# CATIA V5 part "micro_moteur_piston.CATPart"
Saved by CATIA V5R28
Part number: Part6
Bounding box of the stored display mesh (mm): x -13 to 13, y -13 to 13, z 0 to 14.558
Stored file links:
  D:\SAVE\Mécanique\Cotation ISO\Cotation GPS Exercices\Exo 1 ISO GPS\exo1_piston.CATPart
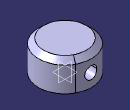
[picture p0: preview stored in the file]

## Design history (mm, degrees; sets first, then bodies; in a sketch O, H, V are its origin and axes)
Body1 (main body)
  Sketch1 on yz-plane, origin (0, 0, 0), H (0, 1, 0), V (0, 0, 1)
    axis line L1 (0, 69.187) -> (0, -68.1492)
    point P1 (0, 69.187)
    construction line L2 (-5, 10) -> (5, 10)
    construction line L3 (5, 10) -> (5, 0)
    construction line L4 (5, 0) -> (-5, 0)
    construction line L5 (-5, 0) -> (-5, 10)
    point P5 (5, 0)
    point P7 (0, 14.5584)
    line L6 (0, 14.5584) -> (10.4832, 14.5584)
    line L7 (10.4832, 14.5584) -> (13, 12.2147)
    line L8 (13, 12.2147) -> (13, 0)
    point P10 (13, 0)
    line L9 (13, 0) -> (11.3219, 0)
    line L10 (0, 10) -> (5, 10)
    point P11 (0, 10)
    line L11 (5, 10) -> (5, 2.6167)
    line L12 (11.3219, 0) -> (11.3219, 2.6167)
    line L13 (11.3219, 2.6167) -> (5, 2.6167)
    point P14 (5, 2.6167)
    length L2 = 10
    length L3 = 10
    distance L1 L8 = 13
    coincidence: P1 V, P5 H, P7 L1, P10 H, P14 L3
    vertical: L1 V, L3 V, L5 V, L8 V, L11 V, L12 V
    horizontal: L2 H, L4 H, L6 H, L9 H, L10 H, L13 H
    symmetry: L3 L5 L1
    midpoint: P11 L2
  Shaft1: profile Sketch1, axis Sketch1.L1, angle 360
  Sketch2 on zx-plane, origin (0, 0, 0), H (-1, 0, 0), V (0, 0, 1)
    circle A1 centre (0, 6.3798) radius 3
    point P1 (0, 6.3798)
    radius A1 = 3
    coincidence: P1 V
  Pocket1: profile Sketch2, direction (0, -1, 0), length 20, mirrored extent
